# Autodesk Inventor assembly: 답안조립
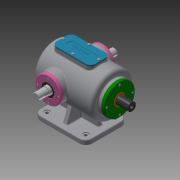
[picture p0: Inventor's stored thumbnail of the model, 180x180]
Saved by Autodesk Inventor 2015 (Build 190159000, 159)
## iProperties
Created: 2021-11
Part Number: 답안조립
Document SubType Name: Assembly
Designer: 101548
Author: 101548
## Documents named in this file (14)
- C:\Users\101548\Desktop\711106V1041\답안조립.iam
- C:\Users\101548\Desktop\711106V1041\베어링 6205.ipt
- 베어링 6205.ipt
- C:\Users\101548\Desktop\711106V1041\본체.ipt
- C:\Users\101548\Desktop\711106V1041\볼트 M4x0.7.ipt
- C:\Users\101548\Desktop\711106V1041\부시.ipt
- C:\Users\101548\Desktop\711106V1041\상부커버.ipt
- C:\Users\101548\Desktop\711106V1041\슬라이드 커버.ipt
- C:\Users\101548\Desktop\711106V1041\슬라이드.ipt
- C:\Users\101548\Desktop\711106V1041\오일실.ipt
- 오일실.ipt
- C:\Users\101548\Desktop\711106V1041\육각머리볼트 M4.ipt
- C:\Users\101548\Desktop\711106V1041\축 커버.ipt
- C:\Users\101548\Desktop\711106V1041\편심축.ipt
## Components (12 placed, 1 different names)
1. M4x0.7:2
2. M4x0.7:3
3. M4x0.7:4
4. M4x0.7:5
5. M4x0.7:1
6. M4x0.7:6
7. M4x0.7:7
8. M4x0.7:8
9. M4x0.7:9
10. M4x0.7:10
11. M4x0.7:11
12. M4x0.7:12
